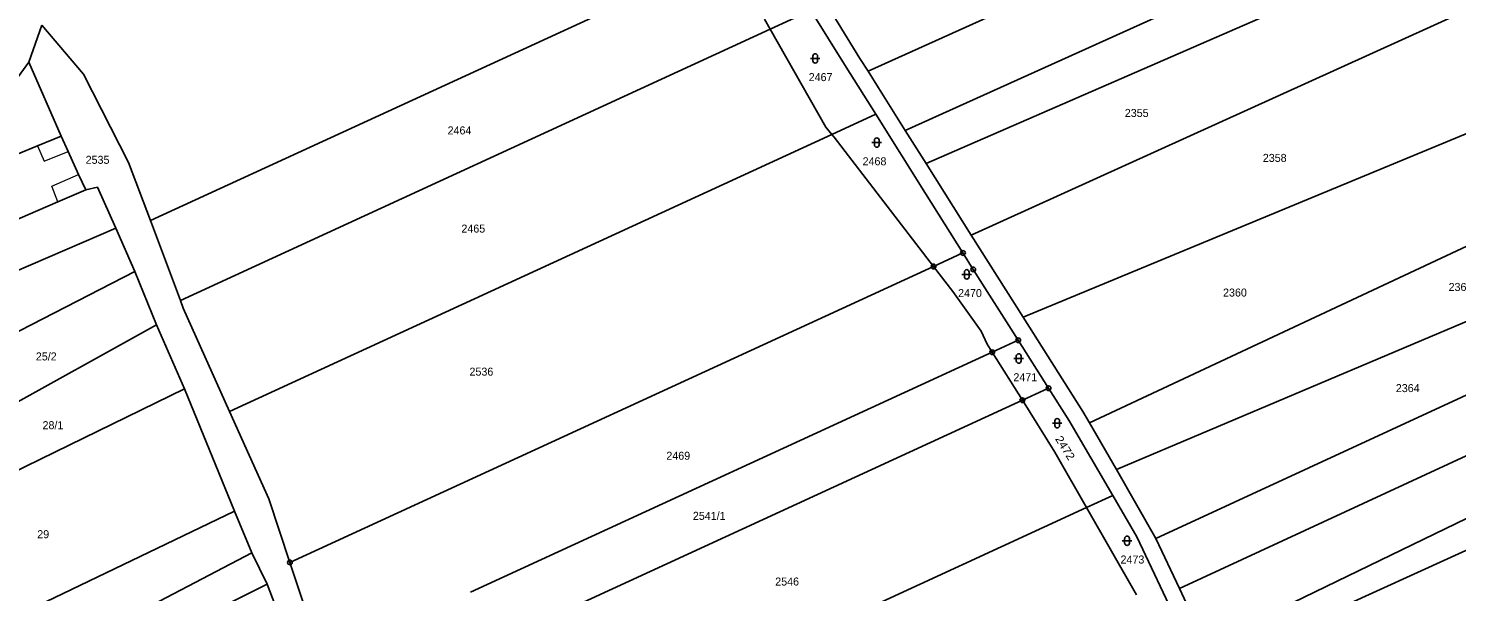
# Model space of a CAD drawing. Extents: x -606517 to -602431, y -1183120 to -1179397.
# Drawn here: x -605326.3 to -605022.9, y -1180857.3 to -1180737.7 of the extents above; entities that cross this region are included whole.
import ezdxf
from ezdxf.enums import TextEntityAlignment as Align

# ---------------------------------------------------------------- set-up
doc = ezdxf.new("R2010")
doc.units = 0
doc.header["$LTSCALE"] = 0.68
for name, color, linetype, lineweight in [('1', 7, 'Continuous', 25), ('3', 7, 'Continuous', 25), ('4', 7, 'Continuous', 13), ('8', 7, 'Continuous', 25)]:
    doc.layers.add(name, color=color, linetype=linetype, lineweight=lineweight)
doc.layers.add('2', color=7, linetype='Continuous')

msp = doc.modelspace()

# ---------------------------------------------------------------- linework, layer by layer
at = {"layer": '1'}
for p, q in [((-605058.13, -1180706.22), (-605147.9, -1180746.78)), ((-605044.77, -1180716.33), (-605139.99, -1180759.35)), ((-605176.91, -1180721.73), (-605300.37, -1180778.51)), ((-605135.59, -1180766.34), (-605036.05, -1180723.03)), ((-605168.67, -1180737.82), (-605169.88, -1180735.68)), ((-605160.07, -1180733.87), (-605168.67, -1180737.82)), ((-605152.59, -1180745.9), (-605160.07, -1180733.87)), ((-605155.63, -1180734.38), (-605149.62, -1180744.04)), ((-605021.53, -1180734.2), (-605125.99, -1180781.59)), ((-605326.18, -1180744.86), (-605323.42, -1180736.98)), ((-605314.62, -1180747.36), (-605323.42, -1180736.98)), ((-605168.67, -1180737.82), (-605294.01, -1180795.46)), ((-605156.87, -1180758.66), (-605168.67, -1180737.82)), ((-605345.64, -1180771.32), (-605326.18, -1180744.86)), ((-605326.18, -1180744.86), (-605319.3, -1180760.56)), ((-605149.62, -1180744.04), (-605147.9, -1180746.78)), ((-605305.01, -1180766.13), (-605314.62, -1180747.36)), ((-605146.29, -1180755.91), (-605152.59, -1180745.9)), ((-605147.9, -1180746.78), (-605145.69, -1180750.3)), ((-605145.69, -1180750.3), (-605139.99, -1180759.35)), ((-605001.77, -1180752.1), (-605114.95, -1180799.05)), ((-605146.29, -1180755.91), (-605155.61, -1180760.19)), ((-605135.69, -1180772.75), (-605146.29, -1180755.91)), ((-605324.37, -1180762.62), (-605319.3, -1180760.56)), ((-605319.3, -1180760.56), (-605317.82, -1180763.79)), ((-605155.61, -1180760.19), (-605283.56, -1180819.04)), ((-605155.61, -1180760.19), (-605156.87, -1180758.66)), ((-605155.14, -1180760.76), (-605155.61, -1180760.19)), ((-605133.98, -1180788.25), (-605155.14, -1180760.76)), ((-605139.99, -1180759.35), (-605135.59, -1180766.34)), ((-605328.85, -1180764.46), (-605324.37, -1180762.62)), ((-605317.82, -1180763.79), (-605315.62, -1180768.68)), ((-605300.37, -1180778.51), (-605305.01, -1180766.13)), ((-605125.99, -1180781.59), (-605135.59, -1180766.34)), ((-605315.62, -1180768.68), (-605314.08, -1180771.94)), ((-605314.08, -1180771.94), (-605320.02, -1180774.54)), ((-605314.08, -1180771.94), (-605311.61, -1180771.39)), ((-605311.61, -1180771.39), (-605307.75, -1180780.1)), ((-605127.74, -1180785.38), (-605135.69, -1180772.75)), ((-605320.02, -1180774.54), (-605332.37, -1180779.85)), ((-605300.37, -1180778.51), (-605294.01, -1180795.46)), ((-605307.75, -1180780.1), (-605353.24, -1180799.73)), ((-605307.75, -1180780.1), (-605303.67, -1180789.29)), ((-605114.95, -1180799.05), (-605125.99, -1180781.59)), ((-604979.97, -1180782.7), (-605095.11, -1180831.36)), ((-605127.74, -1180785.38), (-605133.98, -1180788.25)), ((-605125.55, -1180788.86), (-605127.74, -1180785.38)), ((-605346.34, -1180811.21), (-605303.67, -1180789.29)), ((-605303.67, -1180789.29), (-605299.09, -1180800.63)), ((-605133.98, -1180788.25), (-605270.73, -1180851.13)), ((-605129.91, -1180793.53), (-605133.98, -1180788.25)), ((-605116.01, -1180803.92), (-605125.55, -1180788.86)), ((-605123.91, -1180802.02), (-605129.91, -1180793.53)), ((-605294.01, -1180795.46), (-605293.4, -1180797.08)), ((-605293.4, -1180797.08), (-605283.56, -1180819.04)), ((-605114.95, -1180799.05), (-605102.25, -1180819.09)), ((-605299.09, -1180800.63), (-605342.2, -1180824.58)), ((-605299.09, -1180800.63), (-605293.12, -1180814.25)), ((-605122.58, -1180804.77), (-605123.91, -1180802.02)), ((-604965.22, -1180802.77), (-605081.76, -1180856.63)), ((-605121.52, -1180806.46), (-605122.58, -1180804.77)), ((-605116.01, -1180803.92), (-605121.52, -1180806.46)), ((-605109.55, -1180814.11), (-605116.01, -1180803.92)), ((-605232.39, -1180857.44), (-605121.52, -1180806.46)), ((-605121.52, -1180806.46), (-605115.13, -1180816.68)), ((-605076.11, -1180868.57), (-604959.12, -1180811.92)), ((-605293.12, -1180814.25), (-605336.22, -1180835.26)), ((-605293.12, -1180814.25), (-605282.51, -1180840.21)), ((-605109.55, -1180814.11), (-605115.13, -1180816.68)), ((-605105.24, -1180820.91), (-605109.55, -1180814.11)), ((-605226.86, -1180868.06), (-605115.13, -1180816.68)), ((-605115.13, -1180816.68), (-605108.23, -1180827.69)), ((-605283.56, -1180819.04), (-605275.24, -1180837.62)), ((-605095.92, -1180836.92), (-605105.24, -1180820.91)), ((-605074.12, -1180872.77), (-604955.31, -1180818.73)), ((-605095.11, -1180831.36), (-605100.85, -1180821.49)), ((-605108.23, -1180827.69), (-605101.48, -1180839.48)), ((-605095.11, -1180831.36), (-605086.77, -1180846.05)), ((-605275.24, -1180837.62), (-605270.73, -1180851.13)), ((-605212.57, -1180890.57), (-605101.48, -1180839.48)), ((-605095.92, -1180836.92), (-605101.48, -1180839.48)), ((-605101.48, -1180839.48), (-605090.87, -1180858.03)), ((-605090.81, -1180845.71), (-605095.92, -1180836.92)), ((-605328.07, -1180862.14), (-605282.51, -1180840.21)), ((-605282.51, -1180840.21), (-605278.83, -1180849.07)), ((-605076.35, -1180876.25), (-605090.81, -1180845.71)), ((-605086.77, -1180846.05), (-605081.76, -1180856.63)), ((-605309.84, -1180865.3), (-605278.83, -1180849.07)), ((-605278.83, -1180849.07), (-605275.6, -1180855.73)), ((-605270.73, -1180851.13), (-605263.81, -1180871.89)), ((-605306.16, -1180871.07), (-605275.6, -1180855.73)), ((-605275.6, -1180855.73), (-605270.07, -1180870.16)), ((-605081.76, -1180856.63), (-605076.11, -1180868.57))]:
    msp.add_line(p, q, dxfattribs=at)
for points in [[(-605102.25, -1180819.09), (-605100.85, -1180821.49), (-604989.4, -1180769.3)], [(-605086.77, -1180846.05), (-604972.56, -1180793.28), (-604964.62, -1180789.82)]]:
    msp.add_lwpolyline(points, dxfattribs=at)
at = {"layer": '3'}
for p, q in [((-605160.121, -1180744.041), (-605158.119, -1180744.041)), ((-605159.621, -1180743.541), (-605159.621, -1180744.542)), ((-605158.619, -1180744.542), (-605158.619, -1180743.541)), ((-605147.071, -1180761.921), (-605145.069, -1180761.921)), ((-605146.571, -1180761.421), (-605146.571, -1180762.422)), ((-605145.569, -1180762.422), (-605145.569, -1180761.421)), ((-605127.951, -1180789.921), (-605125.949, -1180789.921)), ((-605127.451, -1180789.421), (-605127.451, -1180790.422)), ((-605126.449, -1180790.422), (-605126.449, -1180789.421)), ((-605116.911, -1180807.801), (-605114.909, -1180807.801)), ((-605116.411, -1180807.301), (-605116.411, -1180808.302)), ((-605115.409, -1180808.302), (-605115.409, -1180807.301)), ((-605108.221, -1180821.051), (-605108.221, -1180822.052)), ((-605107.219, -1180822.052), (-605107.219, -1180821.051)), ((-605108.721, -1180821.551), (-605106.719, -1180821.551)), ((-605093.891, -1180846.531), (-605091.889, -1180846.531)), ((-605093.391, -1180846.031), (-605093.391, -1180847.032)), ((-605092.389, -1180847.032), (-605092.389, -1180846.031))]:
    msp.add_line(p, q, dxfattribs=at)
for centre, start, end in [((-605159.12, -1180743.5409), 0, 180), ((-605159.12, -1180744.5409), 180, 359.98789), ((-605146.07, -1180761.4209), 0, 180), ((-605146.07, -1180762.4209), 180, 359.98789), ((-605126.95, -1180789.4209), 0, 180), ((-605126.95, -1180790.4209), 180, 359.98789), ((-605115.91, -1180807.3009), 0, 180), ((-605115.91, -1180808.3009), 180, 359.98789), ((-605107.72, -1180821.0509), 0, 180), ((-605107.72, -1180822.0509), 180, 359.98789), ((-605092.89, -1180846.0309), 0, 180), ((-605092.89, -1180847.0309), 180, 359.98789)]:
    msp.add_arc(centre, 0.5, start, end, dxfattribs=at)
at = {"layer": '4'}
for p, q in [((-605324.37, -1180762.62), (-605322.94, -1180765.87)), ((-605322.94, -1180765.87), (-605317.82, -1180763.79)), ((-605321.34, -1180771.21), (-605315.62, -1180768.68)), ((-605320.02, -1180774.54), (-605321.34, -1180771.21))]:
    msp.add_line(p, q, dxfattribs=at)
at = {"layer": '8'}
for centre, radius in [((-605127.74, -1180785.3799), 0.5), ((-605133.98, -1180788.2499), 0.5), ((-605127.74, -1180785.3799), 0.0303), ((-605133.98, -1180788.2499), 0.0303), ((-605125.55, -1180788.8599), 0.5), ((-605125.55, -1180788.8599), 0.0303), ((-605121.52, -1180806.4599), 0.5), ((-605116.01, -1180803.9199), 0.5), ((-605116.01, -1180803.9199), 0.0303), ((-605121.52, -1180806.4599), 0.0303), ((-605109.55, -1180814.1099), 0.5), ((-605109.55, -1180814.1099), 0.0303), ((-605115.13, -1180816.6799), 0.5), ((-605115.13, -1180816.6799), 0.0303), ((-605270.73, -1180851.1299), 0.5), ((-605270.73, -1180851.1299), 0.0303)]:
    msp.add_circle(centre, radius, dxfattribs=at)

# ---------------------------------------------------------------- texts
at = {"layer": '2'}
for s, p in [('2467', (-605160.52, -1180748.865)), ('2355', (-605093.36, -1180756.475)), ('2464', (-605237.24, -1180760.185)), ('2535', (-605314.13, -1180766.435)), ('2468', (-605149.07, -1180766.745)), ('2358', (-605064.04, -1180766.025)), ('2465', (-605234.3, -1180781.045)), ('2470', (-605128.78, -1180794.745)), ('2360', (-605072.49, -1180794.635)), ('2363', (-605024.57, -1180793.445)), ('2536', (-605232.58, -1180811.435)), ('2471', (-605117.03, -1180812.625)), ('2364', (-605035.78, -1180814.935)), ('28/1', (-605323.29, -1180822.815)), ('2469', (-605190.76, -1180829.305)), ('29', (-605324.41, -1180845.975)), ('2473', (-605094.27, -1180851.355)), ('2546', (-605167.63, -1180856.035))]:
    msp.add_text(s, height=1.7, dxfattribs=at).set_placement(p)
for s, p in [('25/2', (-605322.499, -1180808.205)), ('2541/1', (-605181.65, -1180842.075))]:
    msp.add_text(s, height=1.7, dxfattribs=at).set_placement(p, align=Align.CENTER)
at = {"layer": '2', "width": 1.1}
msp.add_text('2472', height=1.7, rotation=302, dxfattribs=at).set_placement((-605108.23, -1180824.875))

doc.saveas('drawing.dxf')
